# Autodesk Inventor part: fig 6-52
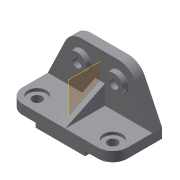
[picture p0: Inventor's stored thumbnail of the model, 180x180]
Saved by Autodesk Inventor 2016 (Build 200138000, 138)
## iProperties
Shininess: 77.0
Length Units: 11269
Angle Units: 11279
Time Units: 11290
Mass Units: 11283
Length Display Precision: 3
Angle Display Precision: 2
Created: 2001-12
Part Number: fig 6-52
Document SubType Name: Modeling
Designer: Renu Muthoo
Density: 1 g/cm^3
Material: Generic
Appearance: Default
Density: 0.0
Volumn: 0.0
Area: 0.0
PropertySet Name: Model Information
Control State: 0
Master: False
Checked Out: False
Author: Renu Muthoo
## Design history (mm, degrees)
node "Sketch1"
sketch "Sketch2"
  geometry: L1 (-67.219, 19.116)-(148.781, 19.116); L2 (148.781, 19.116)-(148.781, -0.884); L3 (-67.219, -0.884)-(-67.219, 19.116); L4 (-10.219, -0.884)-(-10.219, -9.884); L5 (-10.219, -9.884)-(91.781, -9.884); L6 (91.781, -9.884)-(91.781, -0.884); L7 (148.781, -0.884)-(91.781, -0.884); L8 (-10.219, -0.884)-(-67.219, -0.884)
  constraints: 16 end point, 5 parallel, 4 perpendicular, 2 equal length, 1 horizontal
  dimensions: "d0" = 102 distance of L4.end L5.end; "d1" = 57 distance of L4.start L3.start; "d2" = 29 distance between parallel lines of L1 L5; "d3" = 20 distance of L1.end L2.end
extrude "Extrusion1" new body sketch "Sketch2" distance "d4" = 102; taper "d5" = 0 deg
sketch "Sketch3"
  geometry: L1 (67.219, -19.116)-(-148.781, -19.116) reference; L2 (67.219, -19.116)-(31.475, -93.564); L3 (-2.781, -115.116)-(-78.781, -115.116); L4 (-113.038, -93.564)-(-148.781, -19.116); A1 r 38 centre (-2.781, -77.116) between (-2.781, -115.116) and (31.475, -93.564); A2 r 38 centre (-78.781, -77.116) between (-113.038, -93.564) and (-78.781, -115.116)
  constraints: 6 end point, 4 point on circle, 4 tangent, 2 centre point, 1 equal length, 1 equal radius, 1 parallel
  dimensions: "d6" = 96 distance between parallel lines of L3 L1; "d7" = 38 radius of A1; "d8" = 76 distance of A2.centre A1.centre
extrude "Extrusion2" join sketch "Sketch3" distance "d9" = 20; taper "d10" = 0 deg
fillet "Fillet1" dims "d11" = 30
workplane "Work Plane1"
sketch "Sketch5"
  geometry: A1 r 30 centre (-30, 0) between (-30, -30) and (0, 0) reference; 1 further point
  constraints: 1 coincident
hole "Hole1" sketch "Sketch5" at (-30, 0) diameter "d16" = 20; stored, may be unused: countersink angle "d20" = 82 deg, drill point angle "d22" = 118 deg; dims "d17" = 6, "d18" = 38, "d19" = 6, "d21" = 8
sketch "Sketch6"
  geometry: C1 r 19 at (-2.781, 77.116); C2 r 9.5 at (-2.781, 77.116); A1 r 38 centre (-2.781, 77.116) between (31.475, 93.564) and (-2.781, 115.116) reference
  constraints: 2 centre point, 2 coincident
  dimensions: "d23" = 38 diameter of C1; "d24" = 19 diameter of C2
extrude "Extrusion3" join sketch "Sketch6" distance "d25" = 10; taper "d26" = 0 deg
sketch "Sketch7"
  geometry: L1 (0, -82)-(-39.557, 0); L2 (0, -82)-(20, -82) reference; L3 (29, 22.405)-(29, -82); L4 (29, -82)-(0, -82); L5 (0, -82)-(0, 0); L6 (0, 0)-(-90.034, 0); L7 (-90.034, 0)-(-90.034, 22.405); L8 (-90.034, 22.405)-(29, 22.405); L9 (0, 0)-(-74.447, 0) reference
  constraints: 14 end point, 1 collinear, 1 point on line
feature "Rib3" sketch "Sketch7" dims "d35" = 10, "d36" = 20
fillet "Fillet3" dims "d37" = 2
mirror "Mirror4"
body "Solid1"
other parameters: "d12" = -108
